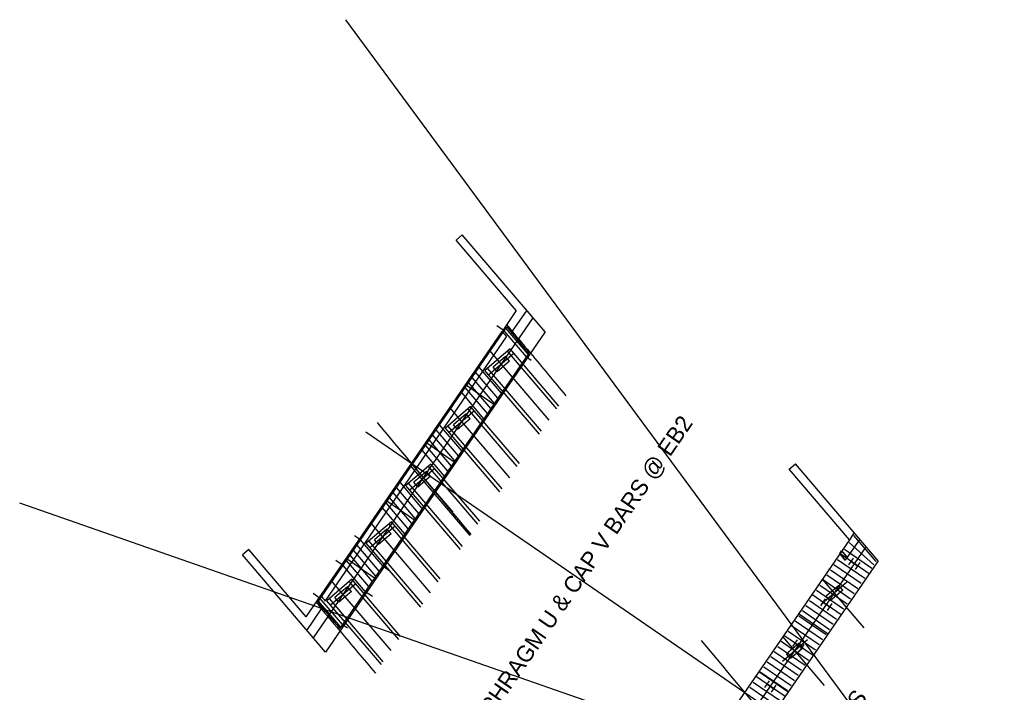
# Model space of a CAD drawing. Extents: x 2378999 to 2381348, y 331302 to 333122.
# Drawn here: x 2379115.2 to 2379234.7, y 331618.1 to 331699.5 of the extents above; entities that cross this region are included whole.
import ezdxf

# ---------------------------------------------------------------- set-up
doc = ezdxf.new("R2010")
doc.units = 0
for name, color, linetype in [('Dimension Lines', 7, 'Continuous'), ('Dimension Lines CELL', 7, 'Continuous'), ('Mis Work Point CELL', 7, 'Continuous'), ('P_NCDOT_Horizontal_Alignment', 7, 'Continuous'), ('P_SMU_Approach_Slab', 7, 'Continuous'), ('P_SMU_Bent_Cap', 7, 'Continuous'), ('P_SMU_Concrete_Barrier_Rail', 7, 'Continuous'), ('P_SMU_D_Deck_Outline', 7, 'Continuous'), ('P_SMU_Deck', 7, 'Continuous'), ('P_SMU_Girder_Concrete', 7, 'Continuous'), ('P_SMU_Mis_L_Lines', 7, 'Continuous'), ('P_SMU_Mis_Long_Chord', 7, 'Continuous'), ('P_SMU_Rebar_B_Bar', 7, 'Continuous'), ('P_SMU_Rebar_U_Bar', 7, 'Continuous'), ('Plan Sheet CELL', 7, 'Continuous'), ('Rebar Lines', 7, 'Continuous'), ('Scratch_Level_0', 7, 'Continuous'), ('Sup Concrete Slab Lines', 7, 'Continuous')]:
    doc.layers.add(name, color=color, linetype=linetype)

msp = doc.modelspace()

# ---------------------------------------------------------------- linework, layer by layer
at = {"layer": 'Dimension Lines'}
for p, q in [((2379316.62, 331479.98), (2379154.62, 331699.5)), ((2379173.8, 331661.87), (2379172.91, 331662.48)), ((2379176.49, 331658.72), (2379177.08, 331658.31)), ((2379368.09, 331552.83), (2379115.15, 331641.03)), ((2379156.42, 331636.57), (2379155.67, 331637.08)), ((2379218.84, 331633.96), (2379216.15, 331637.11)), ((2379218.57, 331633.57), (2379215.57, 331636.27)), ((2379215, 331635.44), (2379218.3, 331633.17)), ((2379154.29, 331633.48), (2379153.41, 331634.09)), ((2379159.11, 331633.42), (2379159.96, 331632.84)), ((2379213.72, 331633.58), (2379217.02, 331631.32)), ((2379214.15, 331634.2), (2379217.45, 331631.94)), ((2379212.87, 331632.35), (2379216.17, 331630.08)), ((2379213.3, 331632.96), (2379216.6, 331630.7)), ((2379212.03, 331631.11), (2379215.32, 331628.84)), ((2379212.45, 331631.73), (2379215.75, 331629.46)), ((2379151.54, 331629.48), (2379150.69, 331630.07)), ((2379156.98, 331630.33), (2379157.84, 331629.75)), ((2379211.6, 331630.49), (2379214.9, 331628.23)), ((2379210.33, 331628.64), (2379213.62, 331626.37)), ((2379210.75, 331629.25), (2379214.05, 331626.99)), ((2379209.48, 331627.4), (2379212.77, 331625.14)), ((2379209.9, 331628.02), (2379213.2, 331625.75)), ((2379154.23, 331626.33), (2379154.83, 331625.92)), ((2379208.63, 331626.16), (2379211.92, 331623.9)), ((2379209.05, 331626.78), (2379212.35, 331624.52)), ((2379208.2, 331625.55), (2379211.5, 331623.28)), ((2379206.93, 331623.69), (2379210.23, 331621.43)), ((2379207.35, 331624.31), (2379210.65, 331622.04)), ((2379206.5, 331623.07), (2379209.8, 331620.81)), ((2379205.65, 331621.84), (2379208.95, 331619.57)), ((2379206.08, 331622.46), (2379209.38, 331620.19)), ((2379204.81, 331620.6), (2379208.1, 331618.34)), ((2379205.23, 331621.22), (2379208.53, 331618.95)), ((2379203.96, 331619.36), (2379207.25, 331617.1)), ((2379203.53, 331618.75), (2379206.83, 331616.48))]:
    msp.add_line(p, q, dxfattribs=at)
at = {"layer": 'Dimension Lines CELL'}
msp.add_line((2379340.37, 331523.67), (2379157.06, 331649.61), dxfattribs=at)
at = {"layer": 'Mis Work Point CELL'}
for p, q in [((2379150.7, 331624.71), (2379177.31, 331663.45)), ((2379191.02, 331597.01), (2379217.64, 331635.75))]:
    msp.add_line(p, q, dxfattribs=at)
at = {"layer": 'P_NCDOT_Horizontal_Alignment'}
msp.add_arc((2384595.51, 336185.59), 7080, 219.900348, 219.972766, dxfattribs=at)
at = {"layer": 'P_SMU_Approach_Slab'}
msp.add_line((2379152.15, 331629.19), (2379174.1, 331661.14), dxfattribs=at)
for radius, start, end in [(7061.33, 219.839771, 219.846793), (7098.67, 219.924281, 219.931263)]:
    msp.add_arc((2384595.51, 336185.59), radius, start, end, dxfattribs=at)
at = {"layer": 'P_SMU_Bent_Cap'}
for p, q in [((2379174.98, 331659.14), (2379171.94, 331656.54)), ((2379170.19, 331652.17), (2379167.15, 331649.58)), ((2379165.4, 331645.2), (2379162.36, 331642.61)), ((2379160.61, 331638.24), (2379157.57, 331635.64)), ((2379155.83, 331631.27), (2379152.78, 331628.67)), ((2379215.3, 331631.44), (2379212.26, 331628.84)), ((2379210.52, 331624.47), (2379207.48, 331621.87))]:
    msp.add_line(p, q, dxfattribs=at)
at = {"layer": 'P_SMU_Concrete_Barrier_Rail'}
for radius, start, end in [(7060.38, 219.837589, 219.874109), (7060.38, 219.874109, 219.928485), (7099.63, 219.926438, 219.96274), (7099.63, 219.96274, 220.016792)]:
    msp.add_arc((2384595.51, 336185.59), radius, start, end, dxfattribs=at)
at = {"layer": 'P_SMU_D_Deck_Outline'}
for p, q in [((2379173.97, 331658.78), (2379172.45, 331657.48)), ((2379174.46, 331658.21), (2379173.97, 331658.78)), ((2379172.94, 331656.91), (2379172.45, 331657.48)), ((2379174.46, 331658.21), (2379172.94, 331656.91)), ((2379169.19, 331651.81), (2379167.66, 331650.51)), ((2379169.67, 331651.24), (2379168.15, 331649.94)), ((2379169.67, 331651.24), (2379169.19, 331651.81)), ((2379168.15, 331649.94), (2379167.66, 331650.51)), ((2379164.4, 331644.84), (2379162.88, 331643.54)), ((2379164.88, 331644.27), (2379163.36, 331642.97)), ((2379164.88, 331644.27), (2379164.4, 331644.84)), ((2379163.36, 331642.97), (2379162.88, 331643.54)), ((2379159.61, 331637.87), (2379158.09, 331636.57)), ((2379160.1, 331637.3), (2379158.58, 331636)), ((2379160.1, 331637.3), (2379159.61, 331637.87)), ((2379158.58, 331636), (2379158.09, 331636.57)), ((2379154.82, 331630.9), (2379153.3, 331629.6)), ((2379155.31, 331630.33), (2379154.82, 331630.9)), ((2379214.3, 331631.07), (2379212.78, 331629.77)), ((2379214.79, 331630.5), (2379214.3, 331631.07)), ((2379155.31, 331630.33), (2379153.79, 331629.03)), ((2379213.27, 331629.2), (2379212.78, 331629.77)), ((2379214.79, 331630.5), (2379213.27, 331629.2)), ((2379153.79, 331629.03), (2379153.3, 331629.6)), ((2379209.51, 331624.1), (2379207.99, 331622.8)), ((2379210, 331623.53), (2379209.51, 331624.1)), ((2379208.48, 331622.23), (2379207.99, 331622.8)), ((2379210, 331623.53), (2379208.48, 331622.23))]:
    msp.add_line(p, q, dxfattribs=at)
at = {"layer": 'P_SMU_Deck'}
for p, q in [((2379174.52, 331659.68), (2379171.48, 331657.08)), ((2379180.43, 331652.76), (2379174.52, 331659.68)), ((2379180.18, 331652.41), (2379174.2, 331659.41)), ((2379178.32, 331649.71), (2379171.79, 331657.35)), ((2379178.08, 331649.35), (2379171.48, 331657.08)), ((2379169.73, 331652.71), (2379166.69, 331650.11)), ((2379175.39, 331645.44), (2379169.41, 331652.44)), ((2379175.64, 331645.8), (2379169.73, 331652.71)), ((2379173.29, 331642.38), (2379166.69, 331650.11)), ((2379173.54, 331642.74), (2379167, 331650.38)), ((2379164.94, 331645.74), (2379161.9, 331643.15)), ((2379170.61, 331638.47), (2379164.62, 331645.47)), ((2379170.85, 331638.83), (2379164.94, 331645.74)), ((2379168.51, 331635.41), (2379161.9, 331643.15)), ((2379168.75, 331635.77), (2379162.22, 331643.42)), ((2379160.15, 331638.77), (2379157.11, 331636.18)), ((2379165.82, 331631.5), (2379159.84, 331638.5)), ((2379166.06, 331631.86), (2379160.15, 331638.77)), ((2379163.72, 331628.45), (2379157.11, 331636.18)), ((2379163.96, 331628.8), (2379157.43, 331636.45)), ((2379155.37, 331631.81), (2379152.32, 331629.21)), ((2379161.03, 331624.53), (2379155.05, 331631.54)), ((2379161.27, 331624.89), (2379155.37, 331631.81)), ((2379158.93, 331621.48), (2379152.32, 331629.21)), ((2379159.17, 331621.83), (2379152.64, 331629.48))]:
    msp.add_line(p, q, dxfattribs=at)
at = {"layer": 'P_SMU_Girder_Concrete'}
for p, q in [((2379215.53, 331633.55), (2379216.1, 331634.38)), ((2379215.82, 331633.96), (2379216.63, 331633.41)), ((2379216.34, 331633), (2379216.91, 331633.82)), ((2379212.14, 331628.61), (2379212.7, 331629.43)), ((2379212.42, 331629.02), (2379213.23, 331628.46)), ((2379212.95, 331628.05), (2379213.51, 331628.87)), ((2379208.74, 331623.66), (2379209.3, 331624.49)), ((2379209.02, 331624.07), (2379209.83, 331623.52)), ((2379209.55, 331623.1), (2379210.12, 331623.93)), ((2379205.34, 331618.72), (2379205.91, 331619.54)), ((2379205.62, 331619.13), (2379206.43, 331618.57)), ((2379206.15, 331618.16), (2379206.72, 331618.98))]:
    msp.add_line(p, q, dxfattribs=at)
at = {"layer": 'P_SMU_Mis_L_Lines'}
for p, q in [((2379179.25, 331651.06), (2379172, 331659.55)), ((2379174.47, 331644.09), (2379167.21, 331652.58)), ((2379169.68, 331637.12), (2379162.42, 331645.61)), ((2379164.89, 331630.15), (2379157.64, 331638.64)), ((2379160.1, 331623.18), (2379152.85, 331631.67)), ((2379217.37, 331625.94), (2379212.33, 331631.84)), ((2379212.58, 331618.97), (2379207.54, 331624.87))]:
    msp.add_line(p, q, dxfattribs=at)
at = {"layer": 'P_SMU_Mis_Long_Chord'}
for centre, start, end in [((2384595.51, 336185.59), 219.829816, 219.972766), ((2384635.84, 336157.89), 219.816017, 219.945167)]:
    msp.add_arc(centre, 7080, start, end, dxfattribs=at)
at = {"layer": 'P_SMU_Rebar_B_Bar'}
for p, q in [((2379167.97, 331672.85), (2379168.73, 331673.49)), ((2379175.27, 331664.31), (2379167.97, 331672.85)), ((2379178.77, 331661.75), (2379168.73, 331673.49)), ((2379176.53, 331664.37), (2379174.78, 331661.83)), ((2379175.27, 331664.31), (2379173.55, 331661.8)), ((2379151.6, 331629.85), (2379173.55, 331661.8)), ((2379178.77, 331661.75), (2379152.15, 331623.01)), ((2379172.68, 331652.89), (2379169.11, 331655.34)), ((2379167.87, 331645.88), (2379164.3, 331648.34)), ((2379208.3, 331645.14), (2379209.06, 331645.79)), ((2379219.09, 331634.04), (2379209.06, 331645.79)), ((2379215.59, 331636.6), (2379208.3, 331645.14)), ((2379163.05, 331638.88), (2379159.48, 331641.33)), ((2379216.18, 331637.45), (2379215.59, 331636.6)), ((2379215.59, 331636.6), (2379190.15, 331599.57)), ((2379216.85, 331636.66), (2379215.1, 331634.12)), ((2379142.88, 331635.41), (2379142.12, 331634.76)), ((2379152.15, 331623.01), (2379142.12, 331634.76)), ((2379149.82, 331627.27), (2379142.88, 331635.41)), ((2379158.24, 331631.87), (2379154.67, 331634.32)), ((2379219.09, 331634.04), (2379192.48, 331595.3)), ((2379149.82, 331627.27), (2379151.6, 331629.85)), ((2379149.91, 331625.63), (2379151.7, 331628.23)), ((2379213.01, 331625.18), (2379209.44, 331627.63)), ((2379208.19, 331618.17), (2379204.62, 331620.63))]:
    msp.add_line(p, q, dxfattribs=at)
msp.add_lwpolyline([(2379214.66, 331635.24), (2379215.32, 331634.44), (2379215.1, 331634.12), (2379214.44, 331634.92)], close=True, dxfattribs=at)
for radius, start, end in [(7060.38, 219.837589, 219.846018), (7060, 219.836735, 219.845164)]:
    msp.add_arc((2384635.84, 336157.89), radius, start, end, dxfattribs=at)
at = {"layer": 'P_SMU_Rebar_U_Bar'}
for p, q in [((2379176.71, 331659.05), (2379174.02, 331662.2)), ((2379176.49, 331658.72), (2379173.8, 331661.87)), ((2379173.47, 331654.33), (2379170.78, 331657.48)), ((2379172.62, 331653.09), (2379169.93, 331656.24)), ((2379173.04, 331653.71), (2379170.35, 331656.86)), ((2379171.77, 331651.86), (2379169.08, 331655.01)), ((2379172.19, 331652.48), (2379169.5, 331655.62)), ((2379171.35, 331651.24), (2379168.66, 331654.39)), ((2379168.68, 331647.36), (2379165.99, 331650.51)), ((2379167.83, 331646.12), (2379165.14, 331649.27)), ((2379168.26, 331646.74), (2379165.57, 331649.89)), ((2379166.98, 331644.89), (2379164.29, 331648.04)), ((2379167.41, 331645.51), (2379164.72, 331648.66)), ((2379166.56, 331644.27), (2379163.87, 331647.42)), ((2379163.47, 331639.77), (2379160.78, 331642.92)), ((2379163.89, 331640.39), (2379161.2, 331643.54)), ((2379162.62, 331638.54), (2379159.93, 331641.69)), ((2379163.04, 331639.16), (2379160.35, 331642.3)), ((2379161.77, 331637.3), (2379159.08, 331640.45)), ((2379162.19, 331637.92), (2379159.5, 331641.07)), ((2379158.68, 331632.81), (2379155.99, 331635.95)), ((2379159.11, 331633.42), (2379156.42, 331636.57)), ((2379157.83, 331631.57), (2379155.14, 331634.72)), ((2379158.26, 331632.19), (2379155.57, 331635.34)), ((2379156.98, 331630.33), (2379154.29, 331633.48)), ((2379157.41, 331630.95), (2379154.72, 331634.1)), ((2379154.01, 331626.01), (2379151.32, 331629.15)), ((2379154.23, 331626.33), (2379151.54, 331629.48))]:
    msp.add_line(p, q, dxfattribs=at)
at = {"layer": 'Plan Sheet CELL'}
msp.add_line((2379167.61, 331639.92), (2379162.57, 331645.82), dxfattribs=at)
at = {"layer": 'Rebar Lines'}
for p, q in [((2379218.01, 331632.46), (2379214.44, 331634.91)), ((2379214.61, 331627.51), (2379211.04, 331629.97)), ((2379211.21, 331622.57), (2379207.64, 331625.02)), ((2379207.81, 331617.62), (2379204.24, 331620.08))]:
    msp.add_line(p, q, dxfattribs=at)
at = {"layer": 'Scratch_Level_0'}
for p, q in [((2379151.24, 331629.04), (2379174.12, 331662.35)), ((2379176.79, 331659.16), (2379153.91, 331625.86))]:
    msp.add_line(p, q, dxfattribs=at)
for radius, start, end in [(7060.54, 219.839373, 219.873083), (7099.46, 219.927459, 219.96097)]:
    msp.add_arc((2384595.51, 336185.59), radius, start, end, dxfattribs=at)

# ---------------------------------------------------------------- texts
at = {"layer": 'Sup Concrete Slab Lines'}
for s, p in [('INTEGRAL DIAPHRAGM U & CAP V BARS @ EB2', (2379161.87, 331599.96)), ('EB2 STIRRUPS', (2379206.9, 331601.61))]:
    msp.add_text(s, height=2, rotation=55.5093, dxfattribs=at).set_placement(p)

doc.saveas('drawing.dxf')
